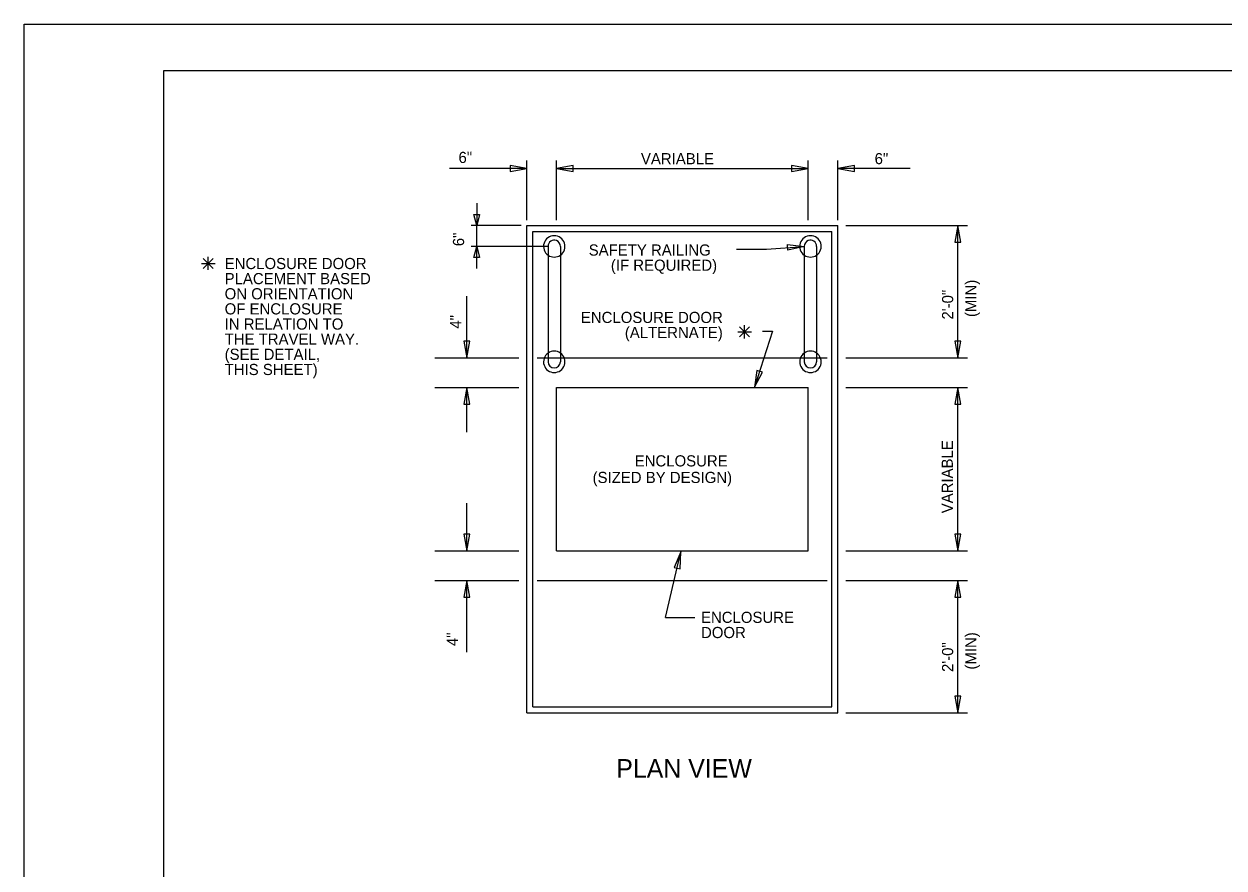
# Model space of a CAD drawing. Extents: x 1299104.8 to 1299141.6, y 239639.8 to 239661.8.
# Drawn here: x 1299104.8 to 1299117.69, y 239652.72 to 239661.79 of the extents above; entities that cross this region are included whole.
import ezdxf

# ---------------------------------------------------------------- set-up
doc = ezdxf.new("R2010")
doc.units = 0
for name, color, linetype in [('DIM TXT', 7, 'Continuous'), ('GS_plotshape_p', 7, 'Continuous'), ('Level 1', 7, 'Continuous'), ('PTEXT', 7, 'Continuous')]:
    doc.layers.add(name, color=color, linetype=linetype)

msp = doc.modelspace()

# ---------------------------------------------------------------- linework, layer by layer
at = {"layer": 'DIM TXT'}
for p, q in [((1299109.664, 239659.866), (1299109.664, 239659.626)), ((1299110.143, 239659.626), (1299109.604, 239659.626)), ((1299109.664, 239659.402), (1299109.664, 239659.626)), ((1299110.437, 239659.402), (1299109.604, 239659.402)), ((1299109.664, 239659.163), (1299109.664, 239659.402))]:
    msp.add_line(p, q, dxfattribs=at)
for points in [[(1299109.694, 239659.746), (1299109.664, 239659.626), (1299109.634, 239659.746)], [(1299109.634, 239659.282), (1299109.664, 239659.402), (1299109.694, 239659.282)]]:
    msp.add_lwpolyline(points, close=True, dxfattribs=at)
at = {"layer": 'GS_plotshape_p'}
msp.add_lwpolyline([(1299104.802, 239661.791), (1299138.802, 239661.791), (1299138.802, 239639.791), (1299104.802, 239639.791)], close=True, dxfattribs=at)
at = {"layer": 'Level 1'}
msp.add_lwpolyline([(1299138.302, 239640.291), (1299106.302, 239640.291), (1299106.302, 239661.291), (1299138.302, 239661.291)], close=True, dxfattribs=at)
at = {"layer": 'PTEXT'}
for p, q in [((1299110.203, 239659.684), (1299110.203, 239660.325)), ((1299110.521, 239659.684), (1299110.521, 239660.325)), ((1299113.225, 239659.684), (1299113.225, 239660.325)), ((1299113.543, 239659.684), (1299113.543, 239660.325)), ((1299110.203, 239660.239), (1299109.373, 239660.239)), ((1299110.203, 239660.239), (1299110.023, 239660.271)), ((1299110.023, 239660.271), (1299110.023, 239660.207)), ((1299110.023, 239660.207), (1299110.203, 239660.239)), ((1299110.701, 239660.271), (1299110.521, 239660.239)), ((1299110.521, 239660.239), (1299113.225, 239660.239)), ((1299110.521, 239660.239), (1299110.701, 239660.207)), ((1299110.701, 239660.207), (1299110.701, 239660.271)), ((1299113.225, 239660.239), (1299113.045, 239660.271)), ((1299113.045, 239660.271), (1299113.045, 239660.207)), ((1299113.045, 239660.207), (1299113.225, 239660.239)), ((1299113.723, 239660.271), (1299113.543, 239660.239)), ((1299114.319, 239660.239), (1299113.543, 239660.239)), ((1299113.543, 239660.239), (1299113.723, 239660.207)), ((1299113.723, 239660.207), (1299113.723, 239660.271)), ((1299110.203, 239659.626), (1299113.543, 239659.626)), ((1299110.203, 239654.391), (1299110.203, 239659.626)), ((1299110.267, 239654.455), (1299110.267, 239659.563)), ((1299110.267, 239659.563), (1299113.479, 239659.563)), ((1299113.479, 239654.455), (1299113.479, 239659.563)), ((1299113.543, 239654.391), (1299113.543, 239659.626)), ((1299113.629, 239659.626), (1299114.935, 239659.626)), ((1299114.831, 239659.626), (1299114.8, 239659.446)), ((1299114.831, 239658.205), (1299114.831, 239659.626)), ((1299114.863, 239659.446), (1299114.831, 239659.626)), ((1299110.431, 239659.402), (1299110.431, 239658.162)), ((1299110.563, 239659.402), (1299110.563, 239658.162)), ((1299113.001, 239659.423), (1299113.183, 239659.402)), ((1299113.005, 239659.36), (1299113.001, 239659.423)), ((1299113.183, 239659.402), (1299113.005, 239659.36)), ((1299113.183, 239659.402), (1299113.183, 239658.162)), ((1299113.315, 239659.402), (1299113.315, 239658.162)), ((1299114.8, 239659.446), (1299114.863, 239659.446)), ((1299109.557, 239658.204), (1299109.557, 239658.867)), ((1299112.841, 239658.49), (1299112.649, 239657.888)), ((1299112.733, 239658.49), (1299112.841, 239658.49)), ((1299109.525, 239658.384), (1299109.557, 239658.204)), ((1299109.589, 239658.384), (1299109.525, 239658.384)), ((1299109.557, 239658.204), (1299109.589, 239658.384)), ((1299114.8, 239658.385), (1299114.831, 239658.205)), ((1299114.863, 239658.385), (1299114.8, 239658.385)), ((1299114.831, 239658.205), (1299114.863, 239658.385)), ((1299109.215, 239658.204), (1299110.117, 239658.204)), ((1299110.313, 239658.204), (1299113.427, 239658.204)), ((1299113.629, 239658.205), (1299114.935, 239658.205)), ((1299112.674, 239658.07), (1299112.649, 239657.888)), ((1299112.649, 239657.888), (1299112.734, 239658.05)), ((1299112.734, 239658.05), (1299112.674, 239658.07)), ((1299109.215, 239657.886), (1299110.117, 239657.886)), ((1299109.557, 239657.886), (1299109.525, 239657.706)), ((1299109.557, 239657.408), (1299109.557, 239657.886)), ((1299109.589, 239657.706), (1299109.557, 239657.886)), ((1299110.521, 239656.131), (1299110.521, 239657.887)), ((1299110.521, 239657.887), (1299113.225, 239657.887)), ((1299113.225, 239656.131), (1299113.225, 239657.887)), ((1299113.629, 239657.887), (1299114.935, 239657.887)), ((1299114.831, 239657.887), (1299114.8, 239657.707)), ((1299114.831, 239656.131), (1299114.831, 239657.887)), ((1299114.863, 239657.707), (1299114.831, 239657.887)), ((1299109.525, 239657.706), (1299109.589, 239657.706)), ((1299114.8, 239657.707), (1299114.863, 239657.707)), ((1299109.557, 239656.131), (1299109.557, 239656.645)), ((1299109.525, 239656.311), (1299109.557, 239656.131)), ((1299109.589, 239656.311), (1299109.525, 239656.311)), ((1299109.557, 239656.131), (1299109.589, 239656.311)), ((1299114.8, 239656.311), (1299114.831, 239656.131)), ((1299114.863, 239656.311), (1299114.8, 239656.311)), ((1299114.831, 239656.131), (1299114.863, 239656.311)), ((1299109.215, 239656.131), (1299110.117, 239656.131)), ((1299110.521, 239656.131), (1299113.225, 239656.131)), ((1299111.691, 239655.416), (1299111.858, 239656.121)), ((1299111.858, 239656.121), (1299111.786, 239655.953)), ((1299111.848, 239655.938), (1299111.858, 239656.121)), ((1299113.629, 239656.131), (1299114.935, 239656.131)), ((1299111.786, 239655.953), (1299111.848, 239655.938)), ((1299109.215, 239655.813), (1299110.117, 239655.813)), ((1299109.557, 239655.813), (1299109.525, 239655.633)), ((1299109.557, 239655.042), (1299109.557, 239655.813)), ((1299109.589, 239655.633), (1299109.557, 239655.813)), ((1299110.313, 239655.813), (1299113.427, 239655.813)), ((1299113.629, 239655.813), (1299114.935, 239655.813)), ((1299114.831, 239655.813), (1299114.8, 239655.633)), ((1299114.831, 239654.391), (1299114.831, 239655.813)), ((1299114.863, 239655.633), (1299114.831, 239655.813)), ((1299109.525, 239655.633), (1299109.589, 239655.633)), ((1299114.8, 239655.633), (1299114.863, 239655.633)), ((1299111.691, 239655.416), (1299112.008, 239655.416)), ((1299114.8, 239654.571), (1299114.831, 239654.391)), ((1299114.863, 239654.571), (1299114.8, 239654.571)), ((1299114.831, 239654.391), (1299114.863, 239654.571)), ((1299110.203, 239654.391), (1299113.543, 239654.391)), ((1299110.267, 239654.455), (1299113.479, 239654.455)), ((1299113.629, 239654.391), (1299114.935, 239654.391))]:
    msp.add_line(p, q, dxfattribs=at)
for points in [[(1299112.455, 239659.372), (1299112.776, 239659.372), (1299113.183, 239659.402)], [(1299106.726, 239659.166), (1299106.833, 239659.273)], [(1299106.833, 239659.166), (1299106.726, 239659.273)], [(1299106.78, 239659.149), (1299106.78, 239659.29)], [(1299106.709, 239659.22), (1299106.854, 239659.22)], [(1299112.47, 239658.484), (1299112.615, 239658.484)], [(1299112.487, 239658.43), (1299112.594, 239658.537)], [(1299112.594, 239658.43), (1299112.487, 239658.537)], [(1299112.541, 239658.413), (1299112.541, 239658.555)]]:
    msp.add_lwpolyline(points, dxfattribs=at)
for centre, radius, start, end in [((1299110.497, 239659.402), 0.115, 305.152, 234.8494), ((1299113.249, 239659.402), 0.115, 305.152, 234.8494), ((1299110.497, 239659.402), 0.0661, 69.0442, 180), ((1299110.497, 239659.402), 0.0661, 0, 69.0464), ((1299113.249, 239659.402), 0.0661, 110.9536, 180), ((1299113.249, 239659.402), 0.0661, 0, 110.9558), ((1299110.497, 239659.402), 0.115, 234.8494, 305.152), ((1299113.249, 239659.402), 0.115, 234.8494, 305.152), ((1299110.497, 239658.162), 0.115, 125.1506, 54.848), ((1299110.497, 239658.162), 0.115, 54.848, 125.1506), ((1299113.249, 239658.162), 0.115, 125.1506, 54.848), ((1299113.249, 239658.162), 0.115, 54.848, 125.1506), ((1299110.497, 239658.162), 0.0661, 180, 0), ((1299113.249, 239658.162), 0.0661, 180, 360)]:
    msp.add_arc(centre, radius, start, end, dxfattribs=at)

# ---------------------------------------------------------------- texts
at = {"layer": 'DIM TXT'}
msp.add_text('6"', height=0.12, rotation=90, dxfattribs=at).set_placement((1299109.529, 239659.404))
at = {"layer": 'PTEXT'}
for s, rotation, p in [('6" ', 360, (1299109.469, 239660.298)), ('6" ', 360, (1299113.938, 239660.285)), ('(MIN)', 90, (1299115.032, 239658.643)), ('2\'-0"', 90, (1299114.782, 239658.616)), ('4" ', 90, (1299109.499, 239658.518)), ('VARIABLE', 90, (1299114.778, 239656.535)), ('4" ', 90, (1299109.463, 239655.108)), ('2\'-0"', 90, (1299114.782, 239654.83)), ('(MIN)', 90, (1299115.032, 239654.856))]:
    msp.add_text(s, height=0.12, rotation=rotation, dxfattribs=at).set_placement(p)
for s, height, p in [('VARIABLE', 0.12, (1299111.428, 239660.284)), ('SAFETY RAILING', 0.12, (1299110.867, 239659.303)), ('ENCLOSURE DOOR ', 0.12, (1299106.957, 239659.158)), ('(IF REQUIRED)', 0.12, (1299111.105, 239659.14)), ('PLACEMENT BASED', 0.12, (1299106.957, 239658.996)), ('ON ORIENTATION', 0.12, (1299106.957, 239658.833)), ('OF ENCLOSURE', 0.12, (1299106.957, 239658.671)), ('IN RELATION TO', 0.12, (1299106.957, 239658.508)), ('ENCLOSURE DOOR', 0.12, (1299110.783, 239658.579)), ('(ALTERNATE)', 0.12, (1299111.255, 239658.417)), ('THE TRAVEL WAY.', 0.12, (1299106.957, 239658.346)), ('(SEE DETAIL,', 0.12, (1299106.957, 239658.183)), ('THIS SHEET)', 0.12, (1299106.957, 239658.02)), ('ENCLOSURE', 0.12, (1299111.361, 239657.038)), ('(SIZED BY DESIGN)', 0.12, (1299110.909, 239656.86)), ('ENCLOSURE', 0.12, (1299112.073, 239655.357)), ('DOOR', 0.12, (1299112.073, 239655.194)), ('PLAN VIEW', 0.2, (1299111.163, 239653.694))]:
    msp.add_text(s, height=height, dxfattribs=at).set_placement(p)

doc.saveas('drawing.dxf')
